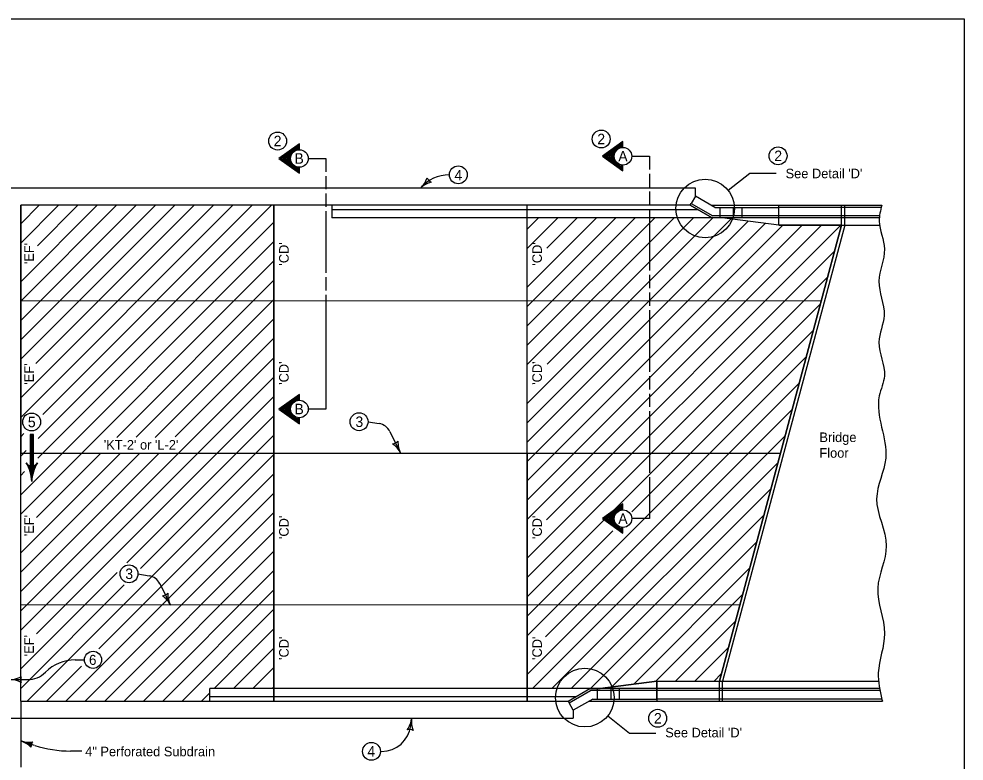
# Model space of a CAD drawing. Extents: x 9234 to 81668, y 5635 to 15999.
# Drawn here: x 22411 to 24068, y 8643 to 9944 of the extents above; entities that cross this region are included whole.
import ezdxf

# ---------------------------------------------------------------- set-up
doc = ezdxf.new("R2010")
doc.units = 0
for name, color, linetype in [('Annotation', 7, 'Continuous'), ('Level 61', 7, 'Continuous'), ('PS_BOLT', 7, 'Continuous'), ('PS_DIM', 7, 'Continuous'), ('Revetment', 7, 'Continuous')]:
    doc.layers.add(name, color=color, linetype=linetype)

msp = doc.modelspace()

# ---------------------------------------------------------------- linework, layer by layer
for p, q in [((23596.7, 9647.3), (22164.9, 9647.3)), ((23596.7, 9633.4), (23596.7, 9647.3)), ((23923.4, 8750.8), (23924.3, 8747.8)), ((21950.3, 8717.8), (23382.5, 8717.9)), ((23382.5, 8731.8), (23382.5, 8717.9))]:
    msp.add_line(p, q)
msp.add_spline([(23923.2, 9617.3), (23918.8, 9589.6), (23927.9, 9540.5), (23918.1, 9484.3), (23927.3, 9424.1), (23918.1, 9377), (23927.9, 9318.2), (23918.8, 9282.9), (23930.1, 9173.6), (23914.2, 9102.7), (23931.1, 9019.9), (23916.2, 8946), (23928.1, 8866.2), (23917.1, 8797.3), (23923.4, 8750.8)], degree=3)
at = {"layer": 'Annotation'}
for p, q in [((23596.7, 9633.4), (23589.3, 9620.5)), ((23630.8, 9613.6), (23596.7, 9633.4)), ((23587.4, 9617.3), (23589.3, 9620.5)), ((23587.4, 9617.3), (23625.9, 9595.1)), ((23589.3, 9620.5), (23626.9, 9598.8)), ((23624.4, 9617.3), (23742.9, 9617.3)), ((23639.3, 9613.6), (23639.3, 9595.1)), ((23662.9, 9613.6), (23662.9, 9595.1)), ((23677.7, 9613.6), (23677.7, 9595.1)), ((23742.9, 9617.3), (23923.2, 9617.3)), ((23742.9, 9582.2), (23742.9, 9617.3)), ((23922.1, 9613.6), (23742.9, 9613.6)), ((23852.7, 9582.2), (23852.7, 9617.3)), ((23852.7, 9582.2), (23852.7, 9617.3)), ((23858.2, 9582.2), (23858.2, 9617.3)), ((23742.9, 9595.1), (23625.9, 9595.1)), ((23742.9, 9598.8), (23626.9, 9598.8)), ((23742.9, 9582.2), (23643.4, 9595.1)), ((23919.5, 9598.8), (23742.9, 9598.8)), ((23919.2, 9595.1), (23742.9, 9595.1)), ((23852.7, 9582.2), (23638.6, 8783)), ((23852.7, 9582.2), (23638.6, 8783)), ((23742.9, 9582.2), (23919, 9582.2)), ((23528.7, 8783), (23429.3, 8770)), ((23528.7, 8783), (23918, 8783)), ((23528.7, 8783), (23528.7, 8747.8)), ((23528.7, 8751.5), (23528.7, 8783)), ((23638.6, 8747.8), (23638.6, 8783)), ((23638.6, 8747.8), (23638.6, 8783)), ((23644.1, 8747.8), (23644.1, 8783)), ((23373.3, 8747.9), (23411.7, 8770)), ((23375.1, 8744.6), (23412.7, 8766.3)), ((23528.7, 8770), (23411.7, 8770)), ((23528.7, 8766.3), (23412.7, 8766.3)), ((23425.1, 8751.5), (23425.1, 8770)), ((23448.7, 8751.5), (23448.7, 8770)), ((23463.5, 8751.5), (23463.5, 8770)), ((23919.5, 8770), (23528.7, 8770)), ((23920, 8766.3), (23528.7, 8766.3)), ((23416.7, 8751.5), (23382.5, 8731.8)), ((23923.2, 8751.5), (23528.7, 8751.5)), ((23373.3, 8747.9), (23375.1, 8744.6)), ((23382.5, 8731.8), (23375.1, 8744.6)), ((23410.3, 8747.8), (23528.7, 8747.8)), ((23528.7, 8747.8), (23924.3, 8747.8))]:
    msp.add_line(p, q, dxfattribs=at)
for points in [[(23630.8, 9613.6), (23742.9, 9613.6), (23742.9, 9613.6), (23742.9, 9613.6)], [(23416.7, 8751.5), (23528.7, 8751.5), (23528.7, 8751.5), (23528.7, 8751.5)]]:
    msp.add_lwpolyline(points, dxfattribs=at)
at = {"layer": 'Level 61'}
msp.add_lwpolyline([(20932.5, 9944), (24067.5, 9944), (24067.5, 7924), (20932.5, 7924)], close=True, dxfattribs=at)
at = {"layer": 'PS_BOLT'}
for p, q in [((23654, 9643.6), (23692.1, 9673.7)), ((23692.1, 9673.7), (23738, 9673.7)), ((22948.6, 9460.3), (22948.6, 9260)), ((23022.7, 9237.7), (23042.2, 9234.4)), ((23061, 9220.4), (23079.6, 9182.6)), ((22619.3, 8971.1), (22638.8, 8967.8)), ((22657.6, 8953.8), (22676.3, 8916)), ((22509.2, 8820.2), (22525.5, 8820.2)), ((22394.6, 8785.6), (22425.9, 8785.6)), ((23097.5, 8704.8), (23099.1, 8717.9)), ((23443.1, 8722.1), (23481.1, 8691.9)), ((23481.1, 8691.9), (23527.1, 8691.9)), ((22521, 8660.3), (22501.3, 8660.3))]:
    msp.add_line(p, q, dxfattribs=at)
for points in [[(22917.7, 9699.2), (22948.6, 9699.2), (22948.6, 9676.1)], [(23485, 9703.1), (23515.8, 9703.1), (23515.8, 9680)], [(22948.6, 9668.4), (22948.6, 9645.3)], [(23515.8, 9672.3), (23515.8, 9649.2)], [(22948.6, 9637.6), (22948.6, 9614.4)], [(23515.8, 9641.5), (23515.8, 9618.3)], [(23515.8, 9610.6), (23515.8, 9502.7)], [(22948.6, 9606.7), (22948.6, 9498.8)], [(23515.8, 9495), (23515.8, 9471.9)], [(22948.6, 9491.1), (22948.6, 9468)], [(23515.8, 9464.2), (23515.8, 9441)], [(23515.8, 9433.3), (23515.8, 9325.4)], [(23515.8, 9317.7), (23515.8, 9294.5)], [(23515.8, 9286.8), (23515.8, 9263.7)], [(22948.6, 9271.5), (22948.6, 9260), (22917.7, 9260)], [(23515.8, 9256), (23515.8, 9148.1)], [(23515.8, 9140.3), (23515.8, 9117.2)], [(23515.8, 9119.8), (23515.8, 9067.8), (23485, 9067.8)]]:
    msp.add_lwpolyline(points, dxfattribs=at)
for centre, radius, start, end in [((23165.1, 9603.9), 66.8, 90, 139.4393), ((23037.9, 9209.1), 25.7, 26.2458, 80.4677), ((22634.6, 8942.4), 25.7, 26.2458, 80.4677), ((22509.2, 8746.8), 73.4, 90, 135), ((22425.9, 8829.6), 44.1, 270, 315), ((23046.5, 8711.2), 51.4, 270, 352.7713), ((22501.3, 8865.9), 205.6, 252.1406, 270)]:
    msp.add_arc(centre, radius, start, end, dxfattribs=at)
at = {"layer": 'PS_DIM'}
for p, q in [((22413.7, 9245.4), (22785.6, 9617.3)), ((22413.7, 9279.4), (22751.6, 9617.3)), ((22413.7, 9347.2), (22683.8, 9617.3)), ((22413.7, 9381.2), (22649.8, 9617.3)), ((22413.7, 9415.1), (22615.9, 9617.3)), ((22413.7, 9449.1), (22581.9, 9617.3)), ((22413.7, 9483), (22548, 9617.3)), ((22413.7, 9550.9), (22480.1, 9617.3)), ((22413.7, 9584.8), (22446.2, 9617.3)), ((22440.1, 9339.7), (22717.7, 9617.3)), ((22443.1, 9546.4), (22514.1, 9617.3)), ((22444.6, 9208.5), (22853.5, 9617.3)), ((22452.6, 9250.4), (22819.5, 9617.3)), ((23923.2, 9617.3), (23923.2, 9617.3)), ((23301.7, 9269.9), (23626.9, 9595.1)), ((23301.7, 9337.8), (23559, 9595.1)), ((23301.7, 9371.7), (23525.1, 9595.1)), ((23301.7, 9405.7), (23491.1, 9595.1)), ((23301.7, 9439.6), (23457.2, 9595.1)), ((23301.7, 9473.6), (23423.3, 9595.1)), ((23301.7, 9541.4), (23355.4, 9595.1)), ((23301.7, 9575.4), (23321.4, 9595.1)), ((23336, 9541.8), (23389.3, 9595.1)), ((23336.7, 9338.9), (23593, 9595.1)), ((22444, 9174), (22857.7, 9587.6)), ((23301.7, 9236), (23658.8, 9593.1)), ((23301.7, 9202), (23688.9, 9589.2)), ((23301.7, 9168.1), (23718.9, 9585.3)), ((23301.7, 9066.3), (23817.6, 9582.2)), ((23301.7, 9100.2), (23783.7, 9582.2)), ((23301.7, 9134.2), (23749.7, 9582.2)), ((23335.4, 9066), (23851.5, 9582.2)), ((22413.7, 9109.7), (22857.7, 9553.7)), ((23301.7, 8998.4), (23840.7, 9537.4)), ((22413.7, 9075.7), (22857.7, 9519.7)), ((22582.1, 9210.2), (22857.7, 9485.8)), ((23301.7, 8964.4), (23828.3, 9491)), ((22413.7, 9449.5), (23817.4, 9450.2)), ((22616.4, 9210.6), (22857.7, 9451.8)), ((23301.7, 8930.5), (23815.8, 9444.7)), ((22649.6, 9209.8), (22857.7, 9417.9)), ((23484.8, 9079.7), (23803.4, 9398.3)), ((22684.7, 9211), (22857.7, 9384)), ((22413.7, 8906), (22857.7, 9350)), ((23301.7, 8862.6), (23791, 9351.9)), ((22413.7, 8872.1), (22857.7, 9316.1)), ((23333.7, 8860.7), (23778.6, 9305.6)), ((22441.2, 8865.6), (22857.7, 9282.1)), ((22599.6, 8990.1), (22857.7, 9248.2)), ((23301.7, 8794.7), (23766.2, 9259.2)), ((22413.7, 9211.5), (22419.1, 9216.9)), ((22433.2, 9160.6), (22433.2, 9215.1)), ((22623.8, 8980.4), (22857.7, 9214.2)), ((23310.9, 8770), (23753.7, 9212.9)), ((22413.7, 9177.5), (22423.5, 9187.4)), ((22413.7, 9007.8), (22588.4, 9182.6)), ((22413.7, 8940), (22656.2, 9182.5)), ((22413.7, 8973.9), (22622.3, 9182.5)), ((22425.2, 8747.8), (22857.7, 9180.3)), ((22441.6, 9069.7), (22554.3, 9182.4)), ((23344.9, 8770), (23741.3, 9166.5)), ((22413.7, 9143.6), (22420.6, 9150.6)), ((22430.1, 9160.7), (22430.1, 9160.7)), ((22436.5, 9160.7), (22436.5, 9160.7)), ((22550.8, 8839.5), (22857.7, 9146.4)), ((23378.8, 8770), (23728.9, 9120.1)), ((22493.1, 8747.8), (22857.7, 9112.4)), ((22527, 8747.8), (22857.7, 9078.5)), ((23412.7, 8770), (23716.5, 9073.8)), ((22561, 8747.8), (22857.7, 9044.5)), ((23301.7, 8896.6), (23451.8, 9046.7)), ((23449.3, 8772.6), (23704, 9027.4)), ((22594.9, 8747.8), (22857.7, 9010.6)), ((23488.3, 8777.7), (23691.6, 8981)), ((22413.7, 8804.2), (22582.7, 8973.2)), ((22628.9, 8747.8), (22857.7, 8976.7)), ((22413.7, 8770.2), (22595.3, 8951.9)), ((22662.8, 8747.8), (22857.7, 8942.7)), ((23527.3, 8782.8), (23679.2, 8934.7)), ((22413.7, 8916.7), (23674.6, 8917.3)), ((22696.7, 8747.8), (22857.7, 8908.8)), ((23561.5, 8783), (23666.8, 8888.3)), ((22752.9, 8770), (22857.7, 8874.8)), ((22786.8, 8770), (22857.7, 8840.9)), ((23595.4, 8783), (23654.3, 8841.9)), ((22459.1, 8747.8), (22520.4, 8809.1)), ((22820.8, 8770), (22857.7, 8806.9)), ((23629.3, 8783), (23641.9, 8795.6)), ((22854.7, 8770), (22857.7, 8773)), ((22730.7, 8747.8), (22745.3, 8762.4)), ((22413.7, 8747.8), (22413.7, 8632.1)), ((22438.2, 8670.2), (22413.7, 8678.1)), ((22413.7, 8678.1), (22432.5, 8672))]:
    msp.add_line(p, q, dxfattribs=at)
for points in [[(23469.5, 9718.6), (23469.5, 9728.8), (23433.6, 9703.1), (23469.5, 9677.4), (23469.5, 9687.7)], [(23468.5, 9686.7), (23468.6, 9679.3), (23435.5, 9703.2), (23468.7, 9727.2), (23468.5, 9719.3), (23467.1, 9718.9), (23467.6, 9724.6), (23437.7, 9703.2), (23467.6, 9681.4), (23467.3, 9686.9), (23466.2, 9687.1), (23466.3, 9683.5), (23439.7, 9703.2), (23466.4, 9722), (23465.8, 9718.8), (23464.7, 9718.5), (23464.8, 9719.6), (23441.9, 9702.9), (23465.2, 9685.4), (23464, 9687.3), (23444, 9702.8), (23456.3, 9712.5), (23455.5, 9710.8), (23446.1, 9702.7), (23455.2, 9695.7), (23454.4, 9697.6), (23448, 9702.5), (23454.4, 9708), (23453.7, 9705.6), (23449.6, 9702.4), (23453.8, 9699.1), (23453.6, 9700.8), (23451.2, 9702.3), (23453.5, 9703.7), (23453.3, 9702.2), (23452.6, 9702.3)], [(22902.3, 9714.7), (22902.3, 9724.9), (22866.3, 9699.2), (22902.3, 9673.5), (22902.3, 9683.8)], [(22901.3, 9682.8), (22901.4, 9675.4), (22868.3, 9699.3), (22901.5, 9723.3), (22901.2, 9715.4), (22899.8, 9715), (22900.4, 9720.7), (22870.4, 9699.3), (22900.4, 9677.5), (22900.1, 9683), (22899, 9683.2), (22899.1, 9679.6), (22872.4, 9699.3), (22899.1, 9718.1), (22898.6, 9714.9), (22897.4, 9714.6), (22897.6, 9715.7), (22874.7, 9699), (22898, 9681.5), (22896.8, 9683.4), (22876.7, 9698.9), (22889, 9708.6), (22888.3, 9706.9), (22878.8, 9698.8), (22888, 9691.8), (22887.1, 9693.7), (22880.7, 9698.6), (22887.1, 9704.1), (22886.5, 9701.7), (22882.4, 9698.5), (22886.6, 9695.2), (22886.3, 9696.9), (22883.9, 9698.4), (22886.3, 9699.8), (22886.1, 9698.3), (22885.3, 9698.4)], [(22902.3, 9275.5), (22902.3, 9285.7), (22866.3, 9260), (22902.3, 9234.3), (22902.3, 9244.6)], [(22901.3, 9243.6), (22901.4, 9236.2), (22868.3, 9260), (22901.5, 9284.1), (22901.2, 9276.2), (22899.8, 9275.8), (22900.4, 9281.5), (22870.4, 9260), (22900.4, 9238.3), (22900.1, 9243.8), (22899, 9244), (22899.1, 9240.3), (22872.4, 9260.1), (22899.1, 9278.9), (22898.6, 9275.7), (22897.4, 9275.4), (22897.6, 9276.5), (22874.7, 9259.8), (22898, 9242.3), (22896.8, 9244.2), (22876.7, 9259.7), (22889, 9269.4), (22888.3, 9267.6), (22878.8, 9259.6), (22888, 9252.6), (22887.1, 9254.5), (22880.7, 9259.3), (22887.1, 9264.9), (22886.5, 9262.4), (22882.4, 9259.3), (22886.6, 9256), (22886.3, 9257.7), (22883.9, 9259.2), (22886.3, 9260.6), (22886.1, 9259.1), (22885.3, 9259.2)], [(22436.3, 9160.7), (22436.3, 9215.1), (22430.1, 9215.1), (22430.1, 9160.7), (22435.4, 9160.9), (22435.6, 9214.4), (22430.7, 9214.3), (22430.9, 9161.9), (22434.5, 9161.7), (22434.8, 9213.6), (22431.5, 9213.5), (22431.5, 9162.6), (22433.8, 9162.4), (22434.1, 9213), (22432.2, 9213), (22432.3, 9163.2)], [(22440.3, 9162.1), (22436.6, 9159.8), (22431.2, 9159.6), (22426.5, 9161.5), (22429.9, 9153.5), (22432.6, 9144.1), (22433.2, 9141.4), (22434.5, 9148.2), (22438, 9158.1), (22439.5, 9161.1), (22428.1, 9160), (22433, 9145.5), (22437.3, 9159.6), (22429.4, 9159.1), (22433.1, 9149.1), (22435.3, 9158.3), (22430.7, 9158.7), (22432.8, 9152.3), (22434.1, 9157.2), (22432, 9157.4), (22432.6, 9155.1)], [(23469.5, 9083.2), (23469.5, 9093.5), (23433.6, 9067.8), (23469.5, 9042.1), (23469.5, 9052.4)], [(23468.5, 9051.4), (23468.6, 9043.9), (23435.5, 9067.8), (23468.7, 9091.9), (23468.5, 9084), (23467.1, 9083.6), (23467.6, 9089.3), (23437.7, 9067.8), (23467.6, 9046), (23467.3, 9051.5), (23466.2, 9051.8), (23466.3, 9048.1), (23439.7, 9067.9), (23466.4, 9086.7), (23465.8, 9083.5), (23464.7, 9083.2), (23464.8, 9084.3), (23441.9, 9067.6), (23465.2, 9050.1), (23464, 9052), (23444, 9067.4), (23456.3, 9077.2), (23455.5, 9075.4), (23446.1, 9067.4), (23455.2, 9060.4), (23454.4, 9062.2), (23448, 9067.1), (23454.4, 9072.6), (23453.7, 9070.2), (23449.6, 9067.1), (23453.8, 9063.8), (23453.6, 9065.5), (23451.2, 9067), (23453.5, 9068.4), (23453.3, 9066.9), (23452.6, 9067)], [(22433.2, 8675.7), (22431.4, 8672.4), (22431, 8668.6), (22427.4, 8672), (22421.2, 8675.6), (22429, 8675), (22432.5, 8675.4), (22430.7, 8672.6), (22430.3, 8670.2), (22428, 8672.4), (22424.6, 8674.6), (22428.9, 8674.5), (22431.2, 8674.5), (22429.8, 8671.6), (22427.4, 8673.7), (22429.8, 8673.6), (22429.5, 8672.6), (22428.6, 8673.2)]]:
    msp.add_lwpolyline(points, dxfattribs=at)
msp.add_lwpolyline([(23852.7, 9582.2), (23742.9, 9582.2), (23643.5, 9595.1), (23625.9, 9595.1), (23587.5, 9617.3), (22857.7, 9617.3), (22857.7, 8747.9), (23373.3, 8747.9), (23373.3, 8747.9), (23411.7, 8770), (23429.3, 8770), (23528.7, 8783), (23638.6, 8783)], close=True, dxfattribs=at)
for centre, radius in [((22864.2, 9729.8), 15.7), ((23431.4, 9733.4), 15.7), ((22902.3, 9699.2), 15.4), ((23469.5, 9703.2), 15.4), ((23741.4, 9703.9), 15.7), ((23180.9, 9670.7), 15.7), ((23613.7, 9611.6), 51.4), ((22902.3, 9260), 15.4), ((22432.9, 9237.3), 15.7), ((23006.9, 9237.7), 15.7), ((23469.5, 9067.8), 15.4), ((22603.6, 8971.1), 15.7), ((22540.5, 8820.2), 15), ((23402.8, 8754), 51.4), ((23530.4, 8717.8), 15.7), ((23028.6, 8659.8), 15.7)]:
    msp.add_circle(centre, radius, dxfattribs=at)
for centre, radius, start, end in [((23084.3, 9679.9), 44.4, 312.7719, 340.8444), ((23141.7, 9672.6), 17.1, 205.0386, 240.5053), ((23144.5, 9614.7), 44.4, 104.6994, 132.7719), ((23063.2, 9216), 17.1, 278.5122, 313.9789), ((23039.8, 9163), 44.4, 26.2455, 54.318), ((23119.5, 9202.2), 44.4, 178.1731, 206.2455), ((22433.2, 9171.9), 11.6, 211.7147, 328.2853), ((22366.9, 9130.9), 66.3, 1.6842, 31.7143), ((22499.4, 9130.9), 66.3, 148.2857, 178.3158), ((22659.8, 8949.3), 17.1, 278.5122, 313.9789), ((22636.5, 8896.3), 44.4, 26.2455, 54.318), ((22716.1, 8935.6), 44.4, 178.1731, 206.2455), ((22394.6, 8827.9), 42.3, 270, 298.0725), ((22394.6, 8743.3), 42.3, 61.9275, 90), ((22430.1, 8785.6), 16.3, 162.2666, 197.7334), ((23055.1, 8723.4), 44.4, 324.6988, 352.7713), ((23143.1, 8712.3), 44.4, 172.7713, 200.8438), ((23094.4, 8680.9), 17.1, 65.0379, 100.5046), ((22400.3, 8636.5), 43.7, 44.0691, 72.1415), ((22427.1, 8719.7), 43.7, 252.1415, 280.214), ((22448.5, 8666.9), 16.9, 144.4082, 179.8749)]:
    msp.add_arc(centre, radius, start, end, dxfattribs=at)
at = {"layer": 'Revetment'}
for p, q in [((22413.7, 8747.8), (22413.7, 9617.3)), ((22857.7, 9617.3), (22413.7, 9617.3)), ((22413.7, 9617.3), (22413.7, 9182.6)), ((22857.7, 9182.6), (22857.7, 9617.3)), ((23301.7, 9617.3), (22857.7, 9617.3)), ((22959.4, 9617.3), (22959.4, 9595.1)), ((23301.7, 9182.6), (23301.7, 9617.3)), ((23587.5, 9617.3), (23301.7, 9617.3)), ((23625.9, 9595.1), (23587.5, 9617.3)), ((23601.3, 9609.3), (22959.4, 9609.3)), ((23625.9, 9595.1), (22959.4, 9595.1)), ((23643.5, 9595.1), (23625.9, 9595.1)), ((23742.9, 9582.2), (23643.5, 9595.1)), ((23858.2, 9582.2), (23644.1, 8783)), ((23852.7, 9582.2), (23742.9, 9582.2)), ((23852.7, 9582.2), (23745.7, 9182.6)), ((23745.7, 9182.6), (23852.7, 9582.2)), ((22413.7, 9182.6), (23745.6, 9182.6)), ((22857.7, 8747.8), (22857.7, 9182.6)), ((22857.7, 9182.6), (22857.7, 8747.9)), ((23301.7, 8747.8), (23301.7, 9182.6)), ((23301.7, 9182.6), (23301.7, 8747.8)), ((23638.6, 8783), (23745.7, 9182.6)), ((23429.3, 8770), (23528.7, 8783)), ((23528.7, 8783), (23638.6, 8783)), ((23411.7, 8770), (22745.3, 8770)), ((22745.3, 8747.8), (22745.3, 8770)), ((23373.3, 8747.9), (23411.7, 8770)), ((23411.7, 8770), (23429.3, 8770)), ((22745.3, 8755.9), (23387.2, 8755.8)), ((22413.7, 8747.8), (22857.7, 8747.8)), ((22857.7, 8747.9), (23301.7, 8747.8)), ((23301.7, 8747.8), (23373.3, 8747.9))]:
    msp.add_line(p, q, dxfattribs=at)

# ---------------------------------------------------------------- texts
at = {"layer": 'PS_BOLT'}
for s, height, p in [('2', 18.4, (23424.5, 9724.2)), ('2', 18.4, (22857.2, 9720.7)), ('A', 18.4, (23461.3, 9694)), ('2', 18.4, (23734.8, 9694.7)), ('B', 18.4, (22893.6, 9690.1)), ('4', 18.4, (23174.1, 9660.9)), ("See Detail 'D'", 16.8, (23754.6, 9664.6)), ('B', 18.4, (22893.6, 9250.8)), ('5', 18.4, (22426.3, 9228.1)), ('3', 18.4, (23000.5, 9228.5)), ('Bridge', 16.8, (23813.9, 9202.1)), ("'KT-2' or 'L-2'", 16.8, (22559.4, 9188.9)), ('Floor', 16.8, (23813.9, 9174.6)), ('A', 18.4, (23461.3, 9058.6)), ('3', 18.4, (22597.1, 8961.9)), ('6', 17.5, (22533.5, 8811.4)), ('2', 18.4, (23523.8, 8708.6)), ("See Detail 'D'", 16.8, (23543.6, 8684.3)), ('4" Perforated Subdrain ', 16.8, (22526.8, 8651.1)), ('4', 18.4, (23021.5, 8650.6))]:
    msp.add_text(s, height=height, dxfattribs=at).set_placement(p)
for s, p in [("'EF'", (22436.8, 9514)), ("'CD'", (22883.5, 9511.4)), ("'CD'", (23327.4, 9511.4)), ("'EF'", (22436.8, 9302.7)), ("'CD'", (22883.5, 9302.4)), ("'CD'", (23327.4, 9302.4)), ("'EF'", (22436.8, 9037)), ("'CD'", (22883.5, 9032)), ("'CD'", (23327.4, 9032)), ("'EF'", (22436.8, 8826.4)), ("'CD'", (22883.5, 8820.1)), ("'CD'", (23327.4, 8820.1))]:
    msp.add_text(s, height=16.8, rotation=90, dxfattribs=at).set_placement(p)

doc.saveas('drawing.dxf')
